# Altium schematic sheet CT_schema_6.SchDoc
size 277 x 170 mm
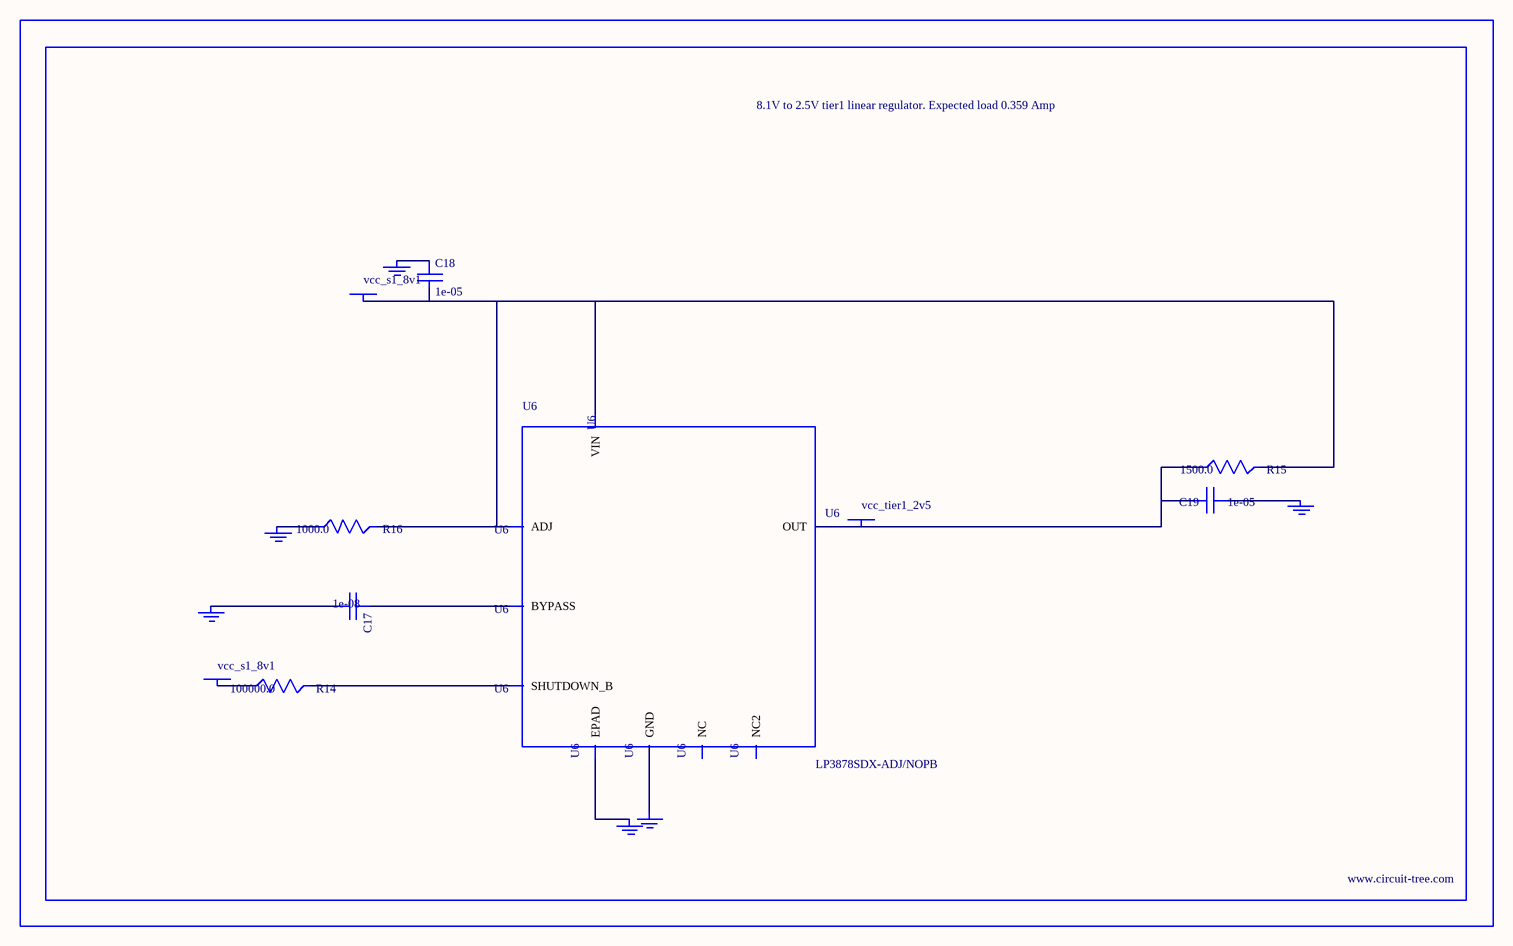
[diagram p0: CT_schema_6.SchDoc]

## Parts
BORDER5  (no value)
C17  1e-08  [C0402]
C18  1e-05  [C1206]
C19  1e-05  [C1210]
GND_INSTANCE_5_0  (no value)
GND_INSTANCE_5_1  (no value)
GND_INSTANCE_5_2  (no value)
GND_INSTANCE_5_3  (no value)
GND_INSTANCE_5_4  (no value)
GND_INSTANCE_5_5  (no value)
POWER_INSTANCE_5_0  vcc_s1_8v1
POWER_INSTANCE_5_1  vcc_s1_8v1
POWER_INSTANCE_5_2  vcc_tier1_2v5
R14  100000.0  [R0603]
R15  1500.0  [R0603]
R16  1000.0  [R0603]
U6  LP3878SDX-ADJ/NOPB  [WSON-8]

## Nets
NetC17_1: C17.1 U6.1(BYPASS)
NetC17_2: C17.2 GND_INSTANCE_5_0.0(GND)
NetC18_1: C18.1 GND_INSTANCE_5_1.0(GND)
NetC18_2: C18.2 POWER_INSTANCE_5_0.0(PWR) R15.2 R16.2 U6.4(VIN) U6.6(ADJ)
NetC19_1: C19.1 GND_INSTANCE_5_2.0(GND)
NetC19_2: C19.2 POWER_INSTANCE_5_2.0(PWR) R15.1 U6.5(OUT)
NetGND_INSTANCE_5_3_0: GND_INSTANCE_5_3.0(GND) R16.1
NetGND_INSTANCE_5_4_0: GND_INSTANCE_5_4.0(GND) U6.PAD(EPAD)
NetGND_INSTANCE_5_5_0: GND_INSTANCE_5_5.0(GND) U6.3(GND)
NetPOWER_INSTANCE_5_1_0: POWER_INSTANCE_5_1.0(PWR) R14.1
NetR14_2: R14.2 U6.8(SHUTDOWN_B)

Not connected (* = marked no-connect by the designer): U6 2(NC) 7(NC2)

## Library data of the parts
BORDER5 = BORDER_PAGE5
C17 = C0402C103K3RAC
C18 = C1206C106K3RACTU
C19 = GRM32DR61E106MA12L
GND_INSTANCE_5_0-GND_INSTANCE_5_5 = GND
POWER_INSTANCE_5_0-POWER_INSTANCE_5_2 = PWR
R14 = RC0603JR-07100KL
R15 = RC0603JR-071K5L
R16 = RC0603JR-071KL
